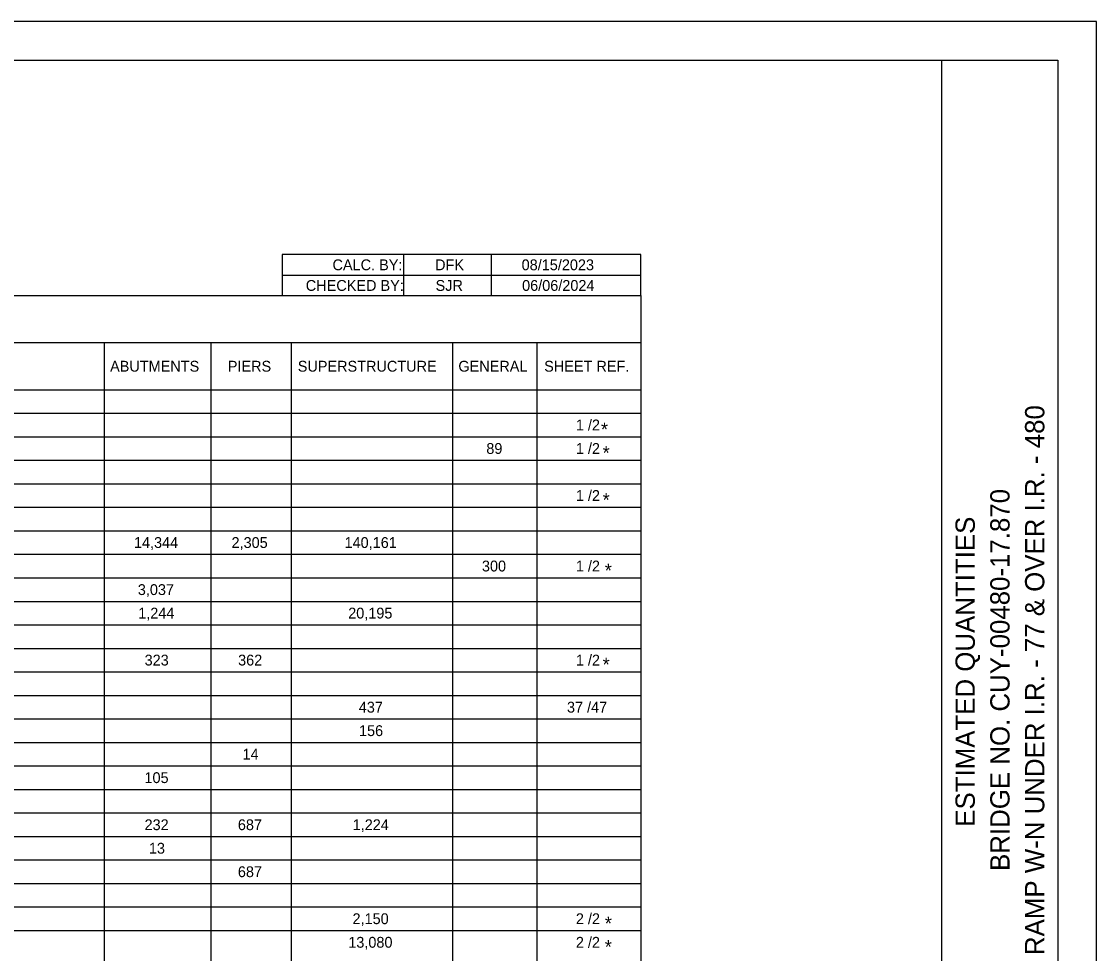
# Model space of a CAD drawing. Extents: x 0 to 34, y 0 to 22.
# Drawn here: x 20.09 to 34, y 9.94 to 22 of the extents above; entities that cross this region are included whole.
import ezdxf

# ---------------------------------------------------------------- set-up
doc = ezdxf.new("R2010")
doc.units = 0
for name, color, linetype in [('SH_Border', 7, 'Continuous'), ('SH_Cut_Line', 7, 'Continuous'), ('SH_Data', 7, 'Continuous'), ('SH_Text', 7, 'Continuous')]:
    doc.layers.add(name, color=color, linetype=linetype)

msp = doc.modelspace()

# ---------------------------------------------------------------- linework, layer by layer
at = {"layer": 'SH_Border'}
msp.add_line((32, 0.5), (32, 21.5), dxfattribs=at)
msp.add_lwpolyline([(1.5, 21.5), (33.5, 21.5), (33.5, 0.5), (1.5, 0.5)], close=True, dxfattribs=at)
at = {"layer": 'SH_Cut_Line'}
msp.add_lwpolyline([(0, 0), (34, 0), (34, 22), (0, 22)], close=True, dxfattribs=at)
at = {"layer": 'SH_Text'}
for p, q in [((25.029, 18.986), (25.029, 18.453)), ((26.165, 18.986), (26.165, 18.453)), ((23.459, 18.719), (28.1, 18.719)), ((5.589, 18.453), (28.1, 18.453)), ((28.1, 18.453), (28.1, 3.851)), ((5.589, 17.845), (28.1, 17.845)), ((21.154, 17.845), (21.154, 3.851)), ((22.535, 17.845), (22.535, 3.851)), ((23.575, 17.845), (23.575, 3.851)), ((25.666, 17.845), (25.666, 3.851)), ((26.756, 17.845), (26.756, 3.851)), ((5.589, 17.236), (28.1, 17.236)), ((5.589, 16.932), (28.1, 16.932)), ((5.589, 16.628), (28.1, 16.628)), ((5.589, 16.324), (28.1, 16.324)), ((5.589, 16.019), (28.1, 16.019)), ((5.589, 15.715), (28.1, 15.715)), ((5.589, 15.411), (28.1, 15.411)), ((5.589, 15.107), (28.1, 15.107)), ((5.589, 14.803), (28.1, 14.803)), ((5.589, 14.498), (28.1, 14.498)), ((5.589, 14.194), (28.1, 14.194)), ((5.589, 13.89), (28.1, 13.89)), ((5.589, 13.586), (28.1, 13.586)), ((5.589, 13.282), (28.1, 13.282)), ((5.589, 12.977), (28.1, 12.977)), ((5.589, 12.673), (28.1, 12.673)), ((5.589, 12.369), (28.1, 12.369)), ((5.589, 12.065), (28.1, 12.065)), ((5.589, 11.761), (28.1, 11.761)), ((5.589, 11.456), (28.1, 11.456)), ((5.589, 11.152), (28.1, 11.152)), ((5.589, 10.848), (28.1, 10.848)), ((5.589, 10.544), (28.1, 10.544)), ((5.589, 10.24), (28.1, 10.24))]:
    msp.add_line(p, q, dxfattribs=at)
msp.add_lwpolyline([(23.459, 18.453), (28.1, 18.453), (28.1, 18.986), (23.459, 18.986)], close=True, dxfattribs=at)

# ---------------------------------------------------------------- texts
at = {"layer": 'SH_Data'}
for s, p in [('RAMP W-N UNDER I.R. - 77 & OVER I.R. - 480', (33.325, 9.922)), ('BRIDGE NO. CUY-00480-17.870', (32.875, 11.01)), ('ESTIMATED QUANTITIES', (32.425, 11.582))]:
    msp.add_text(s, height=0.25, rotation=90, dxfattribs=at).set_placement(p)
at = {"layer": 'SH_Text'}
for s, height, p in [('    08/15/2023', 0.14, (26.351, 18.782)), ('CALC. BY:', 0.14, (24.111, 18.782)), ('    DFK', 0.14, (25.231, 18.782)), ('CHECKED BY:', 0.14, (23.765, 18.515)), ('SJR', 0.14, (25.445, 18.515)), ('06/06/2024', 0.14, (26.565, 18.515)), ('ABUTMENTS', 0.1399, (21.232, 17.47)), ('PIERS', 0.1399, (22.756, 17.47)), ('SUPERSTRUCTURE', 0.13993, (23.661, 17.47)), ('GENERAL', 0.1399, (25.74, 17.47)), ('SHEET REF.', 0.1399, (26.851, 17.47)), ('1 /2', 0.1399, (27.261, 16.71)), ('*', 0.175, (27.586, 16.636)), ('89', 0.1399, (26.102, 16.406)), ('1 /2', 0.1399, (27.261, 16.406)), ('*', 0.175, (27.608, 16.331)), ('1 /2', 0.1399, (27.261, 15.797)), ('*', 0.175, (27.608, 15.723)), ('14,344', 0.1399, (21.541, 15.189)), ('2,305', 0.1399, (22.804, 15.189)), ('140,161', 0.1399, (24.267, 15.189)), ('1 /2', 0.1399, (27.261, 14.885)), ('300', 0.1399, (26.045, 14.885)), ('*', 0.175, (27.636, 14.81)), ('3,037', 0.1399, (21.591, 14.58)), ('1,244', 0.1399, (21.596, 14.276)), ('20,195', 0.1399, (24.314, 14.276)), ('323', 0.1399, (21.679, 13.668)), ('362', 0.1399, (22.889, 13.668)), ('1 /2', 0.1399, (27.261, 13.668)), ('*', 0.175, (27.608, 13.593)), ('437', 0.1399, (24.451, 13.059)), ('37 /47', 0.1399, (27.146, 13.059)), ('156', 0.1399, (24.454, 12.755)), ('14', 0.1399, (22.946, 12.451)), ('105', 0.1399, (21.677, 12.147)), ('232', 0.1399, (21.678, 11.538)), ('687', 0.1399, (22.886, 11.538)), ('1,224', 0.1399, (24.372, 11.538)), ('13', 0.1399, (21.734, 11.234)), ('687', 0.1399, (22.886, 10.93)), ('2,150', 0.1399, (24.37, 10.322)), ('2 /2', 0.1399, (27.261, 10.322)), ('*', 0.175, (27.636, 10.244)), ('13,080', 0.1399, (24.315, 10.017)), ('2 /2', 0.1399, (27.261, 10.017)), ('*', 0.175, (27.636, 9.94))]:
    msp.add_text(s, height=height, dxfattribs=at).set_placement(p)

doc.saveas('drawing.dxf')
